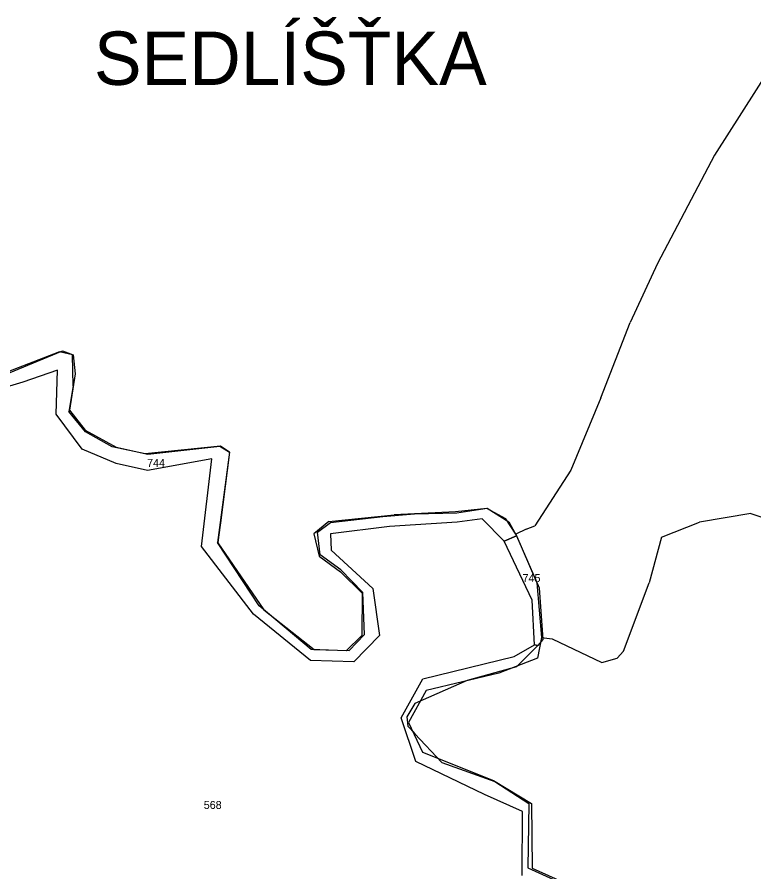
# Model space of a CAD drawing. Extents: x -629983 to -626385, y -1072828 to -1067897.
# Drawn here: x -627364.7 to -627088.6, y -1068989.9 to -1068669.6 of the extents above; entities that cross this region are included whole.
import ezdxf

# ---------------------------------------------------------------- set-up
doc = ezdxf.new("R2010")
doc.units = 0
for name, color, linetype in [('Default', 7, 'Continuous'), ('Katastrální hranice', 7, 'Continuous'), ('Parcela nároku', 7, 'Continuous'), ('Parcelní číslo', 7, 'Continuous')]:
    doc.layers.add(name, color=color, linetype=linetype)

msp = doc.modelspace()

# ---------------------------------------------------------------- linework, layer by layer
at = {"layer": 'Katastrální hranice'}
for p, q in [((-627083.18, -1068689.51), (-627103.43, -1068721.28)), ((-627103.43, -1068721.28), (-627124.73, -1068761.84)), ((-627124.73, -1068761.84), (-627134.99, -1068784.05)), ((-627145.97, -1068812.22), (-627134.99, -1068784.05)), ((-627348.82, -1068794.95), (-627373.68, -1068804.57)), ((-627343.87, -1068796.14), (-627348.82, -1068794.95)), ((-627343.73, -1068807.78), (-627343.87, -1068796.14)), ((-627343.73, -1068807.78), (-627345.27, -1068817.37)), ((-627145.97, -1068812.22), (-627157.2, -1068839.35)), ((-627339.07, -1068825.04), (-627345.27, -1068817.37)), ((-627329.04, -1068830.61), (-627339.07, -1068825.04)), ((-627316.7, -1068833.24), (-627329.04, -1068830.61)), ((-627288.49, -1068830.38), (-627316.7, -1068833.24)), ((-627285.08, -1068832.54), (-627288.49, -1068830.38)), ((-627285.08, -1068832.54), (-627289.61, -1068866.5)), ((-627157.2, -1068839.35), (-627170.7, -1068860.18)), ((-627188.68, -1068853.7), (-627200.45, -1068855.02)), ((-627181.64, -1068857.6), (-627188.68, -1068853.7)), ((-627247.86, -1068858.57), (-627223.41, -1068856.13)), ((-627200.45, -1068855.02), (-627223.41, -1068856.13)), ((-627177.84, -1068863.37), (-627181.64, -1068857.6)), ((-627089.79, -1068855.61), (-627109.07, -1068858.88)), ((-627089.79, -1068855.61), (-627067.21, -1068863.08)), ((-627247.86, -1068858.57), (-627253.5, -1068863.17)), ((-627173.91, -1068861.46), (-627170.7, -1068860.18)), ((-627123.25, -1068864.48), (-627109.07, -1068858.88)), ((-627253.5, -1068863.17), (-627251.55, -1068871.53)), ((-627173.91, -1068861.46), (-627177.84, -1068863.37)), ((-627177.84, -1068863.37), (-627169.96, -1068881.53)), ((-627123.25, -1068864.48), (-627127.92, -1068881.53)), ((-627273.95, -1068890.24), (-627289.61, -1068866.5)), ((-627251.55, -1068871.53), (-627243.47, -1068877.45)), ((-627235.39, -1068885.47), (-627243.47, -1068877.45)), ((-627169.96, -1068881.53), (-627168.19, -1068902.12)), ((-627137.51, -1068907.17), (-627127.92, -1068881.53)), ((-627235.39, -1068885.47), (-627235.47, -1068901.25)), ((-627254.46, -1068906.61), (-627273.95, -1068890.24)), ((-627235.47, -1068901.25), (-627241.39, -1068907.11)), ((-627168.19, -1068902.12), (-627169.68, -1068909.83)), ((-627168.19, -1068902.12), (-627164.21, -1068902.58)), ((-627164.21, -1068902.58), (-627145.59, -1068911.47)), ((-627241.39, -1068907.11), (-627254.46, -1068906.61)), ((-627139.91, -1068909.83), (-627137.51, -1068907.17)), ((-627169.68, -1068909.83), (-627184.15, -1068915.44)), ((-627145.59, -1068911.47), (-627139.91, -1068909.83)), ((-627184.15, -1068915.44), (-627211.46, -1068921.97)), ((-627211.46, -1068921.97), (-627218.05, -1068933.97)), ((-627218.05, -1068933.97), (-627212.76, -1068945.05)), ((-627212.76, -1068945.05), (-627186.16, -1068955.65)), ((-627186.16, -1068955.65), (-627172, -1068964.32)), ((-627172, -1068964.32), (-627171.7, -1068988.54)), ((-627171.7, -1068988.54), (-627148.6, -1068998.82))]:
    msp.add_line(p, q, dxfattribs=at)
at = {"layer": 'Parcela nároku'}
for points in [[(-627371.69, -1068804.54), (-627347.69, -1068794.68), (-627343.74, -1068796.13), (-627342.94, -1068803.26), (-627345.11, -1068816.84), (-627339.2, -1068824.39), (-627327.52, -1068830.76), (-627315.72, -1068833.32), (-627288.78, -1068830.33), (-627285.08, -1068832.57), (-627288.45, -1068859.08), (-627289.11, -1068863.59), (-627289.42, -1068866.64), (-627272.26, -1068891.63), (-627253.41, -1068906.53), (-627240.23, -1068906.97), (-627234.48, -1068900.89), (-627235.17, -1068885.24), (-627243.37, -1068876.67), (-627251.2, -1068871.03), (-627252.08, -1068862.55), (-627247.23, -1068858.9), (-627227.61, -1068856.65), (-627215.84, -1068855.77), (-627199.9, -1068855.3), (-627188.6, -1068853.62), (-627180.52, -1068858.65), (-627177.63, -1068863.92), (-627182.17, -1068865.98), (-627190.45, -1068857.53), (-627199.79, -1068858.78), (-627225.12, -1068860.48), (-627247.33, -1068863.27), (-627247.05, -1068869.36), (-627231.47, -1068883.7), (-627228.9, -1068901.29), (-627238.59, -1068911.2), (-627254.76, -1068910.62), (-627276.11, -1068893.29), (-627295.65, -1068867.99), (-627291.7, -1068835.08), (-627315.79, -1068839.53), (-627327.62, -1068836.85), (-627340.25, -1068831.5), (-627350.09, -1068818.36), (-627349.53, -1068801.91), (-627362.58, -1068806.41), (-627371.38, -1068808.97)], [(-627175.43, -1068991.27), (-627175.34, -1068967.31), (-627189.61, -1068960.84), (-627215.3, -1068948.5), (-627220.83, -1068932.16), (-627212.62, -1068917.52), (-627178.52, -1068909.22), (-627170.85, -1068904.83), (-627171.76, -1068888.1), (-627182.17, -1068865.98), (-627190.45, -1068857.53), (-627199.79, -1068858.78), (-627225.12, -1068860.48), (-627247.33, -1068863.27), (-627247.05, -1068869.36), (-627231.47, -1068883.7), (-627228.9, -1068901.29), (-627238.59, -1068911.2), (-627254.76, -1068910.62), (-627276.11, -1068893.29), (-627295.65, -1068867.99), (-627291.7, -1068835.08), (-627315.79, -1068839.53), (-627327.62, -1068836.85), (-627340.25, -1068831.5), (-627350.09, -1068818.36), (-627349.53, -1068801.91), (-627362.58, -1068806.41), (-627371.38, -1068808.97)], [(-627175.43, -1068991.27), (-627175.34, -1068967.31), (-627189.61, -1068960.84), (-627215.3, -1068948.5), (-627220.83, -1068932.16), (-627212.62, -1068917.52), (-627178.52, -1068909.22), (-627170.85, -1068904.83), (-627169.54, -1068905.1), (-627177.55, -1068913.01), (-627196.11, -1068918.22), (-627215.7, -1068926.82), (-627218.64, -1068931.75), (-627218.3, -1068935.26), (-627217.31, -1068936.33), (-627215.62, -1068938.15), (-627205.62, -1068948.95), (-627185.7, -1068955.97), (-627173.02, -1068964.32), (-627173.36, -1068988.43), (-627150.27, -1068998.85)]]:
    msp.add_lwpolyline(points, dxfattribs=at)
msp.add_lwpolyline([(-627169.05, -1068883.41), (-627167.66, -1068902.77), (-627169.54, -1068905.1), (-627170.85, -1068904.83), (-627171.76, -1068888.1), (-627182.17, -1068865.98), (-627177.63, -1068863.92)], close=True, dxfattribs=at)

# ---------------------------------------------------------------- texts
at = {"layer": 'Default'}
msp.add_text('SEDLÍŠŤKA', height=20, dxfattribs=at).set_placement((-627335.9, -1068694.96))
msp.add_text('SEDLÍŠŤKA', height=20, dxfattribs=at).set_placement((-627335.9, -1068694.96))
at = {"layer": 'Parcelní číslo'}
for s, p in [('744', (-627315.97, -1068838.12)), ('745', (-627175.3, -1068881.26)), ('568', (-627294.75, -1068966.31))]:
    msp.add_text(s, height=3, dxfattribs=at).set_placement(p)

doc.saveas('drawing.dxf')
